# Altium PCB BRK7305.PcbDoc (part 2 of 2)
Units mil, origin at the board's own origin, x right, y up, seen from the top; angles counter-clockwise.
Board outline 4724.41 x 3149.61 mil, 4 copper layers (L1-TOP, L2-GND, L3-PWR, L4-BOT), stack 60.267 mil thick; 97 components, 177 nets, 610 pads, 294 vias.
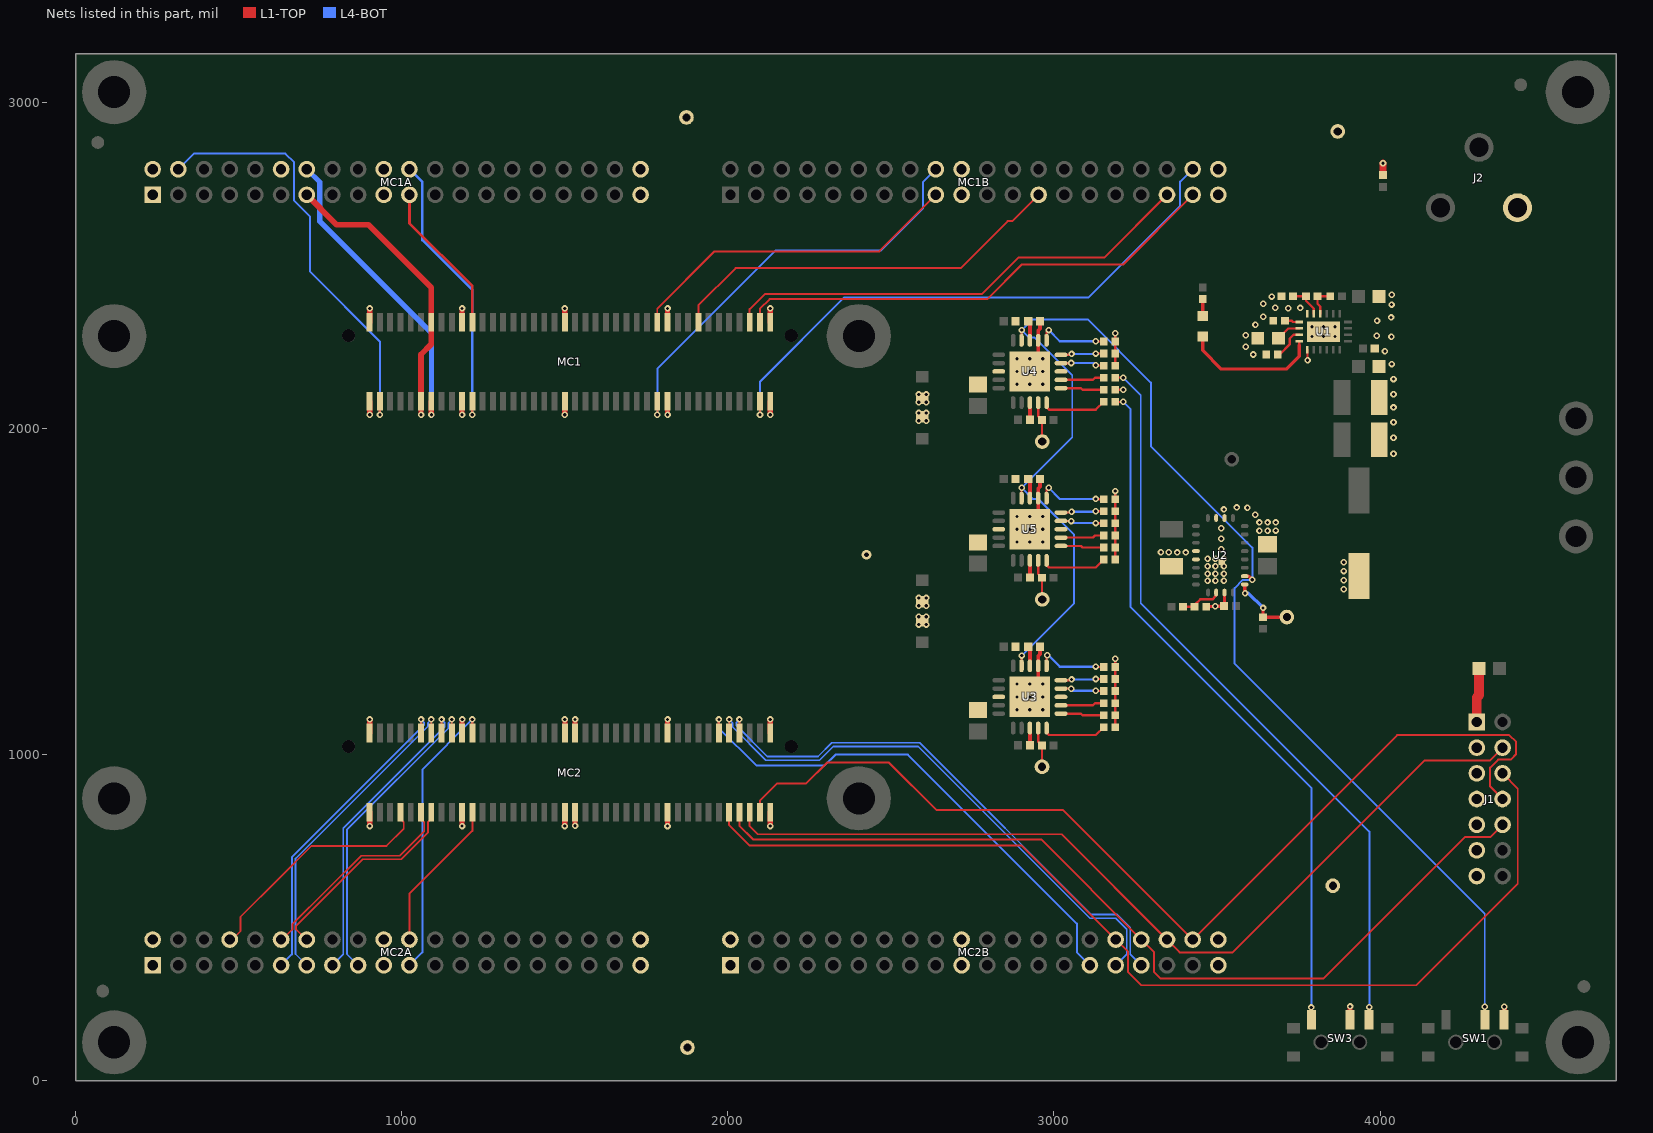
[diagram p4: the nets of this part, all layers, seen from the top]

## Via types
v1: diameter 20, hole 10, L1-TOP to L4-BOT, tented both sides, 293 vias
v2: diameter 30, hole 15, L1-TOP to L4-BOT, tented both sides, 1 vias

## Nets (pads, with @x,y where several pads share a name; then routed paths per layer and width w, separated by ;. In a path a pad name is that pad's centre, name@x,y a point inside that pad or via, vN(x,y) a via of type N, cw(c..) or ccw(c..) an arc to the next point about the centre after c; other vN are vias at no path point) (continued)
B34_L21P: MC2.8 MC2A.8 | length 754.5
  L1-TOP w5.25: MC2A.8@472.44,433.07 479.82,433.07 505.75,459 505.75,502.66 626.09,623 723.34,720.25 953.25,720.25 1006,773 1006,793 996.06,802.94 MC2.8@996.06,823.43
B34_L22N: MC2.14 MC2A.14 | length 646.3
  L1-TOP w5.25: MC2A.14@708.66,433.07 706.93,433.07 676,464 676,475 880,679 998.91,679 1080.25,760.34 1080.25,793 1090.55,803.3 MC2.14@1090.55,823.43
B34_L22P: MC2.12 MC2A.12 | length 648.3
  L1-TOP w5.25: MC2A.12@629.92,433.07 633.82,433.07 664.75,464 664.75,479.66 773.09,588 875.34,690.25 994.25,690.25 1069,765 1069,793 1059.06,802.94 MC2.12@1059.06,823.43
B34_L23N: MC2.17 MC2A.17 | length 942.8
  L1-TOP w5.25: MC2.17@1153.54,1066.34 v1(1153.54,1108)
  L4-BOT w5.25: MC2A.17@866.14,354.33 831.87,388.61 831.87,769.79 1143.42,1081.34 1143.42,1097.88 v1(1153.54,1108)
B34_L23P: MC2.15 MC2A.15 | length 942.3
  L1-TOP w5.25: MC2.15@1122.05,1066.34 v1(1122.05,1108)
  L4-BOT w5.25: MC2A.15@787.4,354.33 820.62,387.55 820.62,774.45 1132.17,1086 1132.17,1097.88 v1(1122.05,1108)
B34_L24N: MC2.13 MC2A.13 | length 981.9
  L1-TOP w5.25: MC2.13@1090.55,1066.34 v1(1090.55,1108)
  L4-BOT w5.25: MC2A.13@708.66,354.33 674.39,388.61 674.39,681.3 1080.43,1087.34 1080.43,1097.88 v1(1090.55,1108)
B34_L24P: MC2.11 MC2A.11 | length 981.5
  L1-TOP w5.25: MC2.11@1059.06,1066.34 v1(1059.06,1108)
  L4-BOT w5.25: MC2A.11@629.92,354.33 663.14,387.55 663.14,685.96 1069.18,1092 1069.18,1097.88 v1(1059.06,1108)
DGND: C1.1 C2.1 C3.2 C4.2 C5.2 C6.1 C7.1 C8.1 C9.1 C10.1 C11.1 C12.1 C14.1 C15.1 C16.1 C17.1 C18.1 C19.1 C20.1 C23.1 C24.1 J1.1 J1.3 J1.5 J1.7 J1.9 J1.11 J1.13 J2.2 MC1.1 MC1.2 MC1.19 MC1.20 MC1.39 MC1.40 MC1.59 MC1.60 MC1.79 MC1.80 MC1A.1 MC1A.2 MC1A.19 MC1A.20 MC1A.39 MC1A.40 MC1B.19 MC1B.20 MC1B.39 MC1B.40 MC2.1 MC2.2 MC2.19 MC2.20 MC2.39 MC2.40 MC2.59 MC2.60 MC2.79 MC2.80 MC2A.1 MC2A.2 MC2A.19 MC2A.20 MC2A.39 MC2A.40 MC2B.19 MC2B.20 MC2B.39 MC2B.40 R3.1 R4.1 R6.1 R7.1 R9.1 R11.1 R13.1 R14.1 R15.1 R16.1 R23.1 R25.1 R26.1 R28.1 R29.1 R30.1 R31.1 R32.1 R33.1 R34.1 SW1.3 SW3.2 TP6.1 TP7.1 TP8.1 TP9.1 U1.1 U1.16 U1.PAD U2.2 U2.3 U2.8 U2.9 U2.15 U2.PAD U3.0 U3.8 U3.12 U3.18 U4.0 U4.8 U4.12 U4.18 U5.0 U5.8 U5.12 U5.18 | length 2290
  L1-TOP w7: R4.1@3187.72,1084 R9.1@3187.72,1195 R11.1@3187.72,1232 R13.1@3187.72,1269 3187.72,1293.72 v1(3188,1294) ; R23.1@3187.72,1598.18 R26.1@3187.72,1635.18 R28.1@3187.72,1672.18 R30.1@3187.72,1709.18 R32.1@3187.72,1746.18 R34.1@3187.72,1783.18 3187.72,1807.9 v1(3188,1808.18) ; R25.1@3187.72,2119 v1(3212,2119) ; R29.1@3187.72,2193 R31.1@3187.72,2230 R33.1@3187.72,2267 3187.72,2291.72 v1(3188,2292) ; U1.1@3777.19,2242.02 3777.19,2209.35 v1(3777.41,2209.14)
  L1-TOP w10: R3.1@3466.43,1454 3493,1454 v1(3494.44,1455.44) C14.1@3521.62,1455.44 ; C14.1@3522.87,1456.44 U2.15@3522.87,1497.27 ; v1(4008.8,2813.45) v1@4009,2813.25
  L1-TOP w12: v1(2926,1177) 2951.59,1202.59 U3.12@2951.59,1272.47 2951.59,1302.59 2957.11,1308.11 C15.1@2957.11,1329 ; v1(2926,1691.18) 2951.59,1716.77 U5.12@2951.59,1786.65 2951.59,1816.77 2957.11,1822.29 C24.1@2957.11,1843.18 ; v1(2926,2175) 2951.59,2200.59 U4.12@2951.59,2270.47 2951.59,2300.59 2957.11,2306.11 C23.1@2957.11,2327
  L1-TOP w15: MC2.39@1500,1066.34 v1(1500,1108) ; SW3.2@3908,187.53 v1(3908,228) ; SW1.3@4379.92,187.01 4381,188.09 v1(4381,227)
  L1-TOP w16: v1(901.51,781.09) v1(901.51,781.09) MC2.2@901.58,823.43 ; MC2.1@901.58,1066.34 901.58,1108 v1(901.64,1108) ; v1(901.58,2042) MC1.2@901.58,2083.27 ; MC1.1@901.58,2326.18 v1(901.58,2368.46) ; v1(1184.98,781.09) 1185.04,781.09 MC2.20@1185.04,823.43 ; MC2.19@1185.04,1066.34 1185.04,1108 v1(1185.1,1108) ; v1(1185.04,2042) MC1.20@1185.04,2083.27 ; MC1.19@1185.04,2326.18 v1(1185.04,2368.46) ; v1(1499.94,781.09) 1500,781.09 MC2.40@1500,823.43 ; v1(1500,2042) MC1.40@1500,2083.27 ; MC1.39@1500,2326.18 v1(1500,2368.46) ; v1(1814.9,781.09) v1(1814.9,781.09) MC2.60@1814.96,823.43 ; MC2.59@1814.96,1066.34 1814.96,1108 v1(1815.02,1108) ; v1(1814.96,2042) MC1.60@1814.96,2083.27 ; MC1.59@1814.96,2326.18 v1(1814.96,2368.46) ; v1(2129.92,781.09) MC2.80@2129.92,823.43 ; MC2.79@2129.92,1066.34 v1(2129.92,1108) ; v1(2129.92,2042) MC1.80@2129.92,2083.27 ; MC1.79@2129.92,2326.18 v1(2129.92,2368.46)
  L1-TOP w22: C6.1@4009,2777.11 v1@4009,2813.25
  L1-TOP w30: J1.1@4296.63,1100.22 4296.63,1175.13 4303.5,1182 C1.1@4303.5,1264
  other v1: 2886.63,1137.63 2926,1137.63 2965.37,1137.63 2886.63,1177 2965.37,1177 2886.63,1216.37 2926,1216.37 2965.37,1216.37 3888.39,1507.4 3471,1533 3495,1533 3521,1533 3888.39,1534.86 3471,1555 3495,1555 3521,1555 3888.39,1562.86 3471,1578 3495,1578 3521,1578 3888.39,1589.86 3471,1601 3495,1601 3521,1601 3378,1620 3404,1620 3328,1621 3352,1621 3513,1630 2886.63,1651.81 2926,1651.81 2965.37,1651.81 3513,1662 3630,1687 3655,1687 3680,1687.26 2886.63,1691.18 2965.37,1691.18 3513,1694 3630,1712 3655,1712 3680,1712 2886.63,1730.55 2926,1730.55 2965.37,1730.55 3617,1736 3521,1752 3593,1757 3560,1758 4041,1923 4041,1971.64 4041,2019.64 4041,2064.64 4041,2105.14 2886.63,2135.63 2926,2135.63 2965.37,2135.63 4041,2151.64 2886.63,2175 2965.37,2175 4035.61,2197.64 2886.63,2214.37 2926,2214.37 2965.37,2214.37 3610.91,2227.04 4014.61,2236.64 3588.21,2250.64 3791.41,2282.14 3826.41,2282.14 3861.41,2282.14 4034.61,2281.64 3989.61,2284.64 3587.81,2286.44 3791.41,2312.14 3826.41,2312.14 3861.41,2312.14 3617.81,2318.34 3990.61,2330.64 4033.61,2340.64 3641.51,2343.04 3718.61,2368.64 3755.41,2369.84 3678.61,2370.64 4035,2380 3641.61,2382.64 3667.71,2404.74 4036,2410
  other v2: 2425,1613
FPGA_TCK: J1.6 MC2.72 MC2B.32 | length 3184.1
  L1-TOP w6: MC2.72@2003.94,823.43 2003.94,784.06 2067,721 2901.05,721 MC2B.32@3188.98,433.07 3227,395.05 3227,333 3267,293 4111,293 4422.06,604.06 4422.06,896.06 J1.6@4375.37,942.74
FPGA_TDI: J1.10 MC2.74 MC2B.34 | length 2807.1
  L1-TOP w6: MC2.74@2035.43,823.43 2035.43,781.57 2077,740 2960.79,740 MC2B.34@3267.72,433.07 3307,393.79 3307,333 3327,313 3826,313 4260,747 4337.11,747 J1.10@4375.37,785.26
FPGA_TDO: J1.8 MC2.78 MC2B.38 | length 3141.8
  L1-TOP w6: MC2.78@2098.43,823.43 2098.43,858.43 2152,912 2240,912 2304,976 2494,976 2639,831 3027.27,831 MC2B.38@3425.2,433.07 4052.13,1060 4396,1060 4417,1039 4417,1002 4400,985 4362,985 4337,960 4337,902.37 J1.8@4375.37,864
FPGA_TMS: J1.4 MC2.76 MC2B.36 | length 2771
  L1-TOP w6: MC2.76@2066.93,823.43 2066.93,781.07 2092,756 3023.53,756 MC2B.36@3346.46,433.07 3385.53,394 3548,394 4136,982 4335.89,982 J1.4@4375.37,1021.48
MC1_4: MC1.4 MC1A.4 | length 1311
  L1-TOP w8: v1@933.07,2041.61 MC1.4@933.07,2083.27
  L4-BOT w6: MC1A.4@314.96,2795.28 362.69,2843 643,2843 670,2816 670,2699 718,2651 718,2482 933.07,2266.93 v1@933.07,2041.61
  other v1: 933.07,2042
MC1_21: MC1.21 MC1A.21 | length 470.3
  L1-TOP w8: MC1A.21@1023.62,2716.54 1023.62,2629.38 1216.54,2436.46 MC1.21@1216.54,2326.18
MC1_22: MC1.22 MC1A.22 | length 875.2
  L1-TOP w8: v1@1216.54,2041.61 MC1.22@1216.54,2083.27
  L4-BOT w8: MC1A.22@1023.62,2795.28 1063,2755.9 1063,2578 1216.54,2424.46 v1@1216.54,2041.61
  other v1: 1216.54,2042
MC1_57: MC1.57 MC1B.17 | length 1040.2
  L1-TOP w6: MC1.57@1783.46,2326.18 1783.46,2367.47 1959,2543 2464.26,2543 MC1B.17@2637.8,2716.54
MC1_58: MC1.58 MC1B.18 | length 1337.6
  L1-TOP w6: MC1.58@1783.46,2083.27 1783.54,2083.2 v1(1783.54,2042)
  L4-BOT w6: v1(1783.54,2042) 1783.54,2183.54 2146.63,2546.63 2469.63,2546.63 2599,2676 2599,2756.48 MC1B.18@2637.8,2795.28
MC1_65: MC1.65 MC1B.25 | length 1235
  L1-TOP w6: MC1.65@1909.45,2326.18 1909.45,2377.45 2024,2492 2714,2492 2858,2636 2872.22,2636 MC1B.25@2952.76,2716.54
MC1_75: MC1.75 MC1B.35 | length 1464.5
  L1-TOP w6: MC1.75@2066.93,2326.18 2066.93,2365.93 2113,2412 2779,2412 2891,2524 3153.92,2524 MC1B.35@3346.46,2716.54
MC1_77: MC1.77 MC1B.37 | length 1512.6
  L1-TOP w6: MC1.77@2098.43,2326.18 2098.43,2367.43 2128,2397 2795,2397 2901,2503 3211.66,2503 MC1B.37@3425.2,2716.54
MC1_78: MC1.78 MC1B.38 | length 1782.9
  L1-TOP w6: MC1.78@2098.43,2083.27 2098.43,2042.07 v1(2098.5,2042)
  L4-BOT w6: v1(2098.5,2042) 2098.5,2143.5 2357,2402 3106,2402 3387,2683 3387,2757.08 MC1B.38@3425.2,2795.28
MC2_21: MC2.21 MC2A.21 | length 875.2
  L1-TOP w8: MC2.21@1216.54,1066.34 v1(1216.54,1108)
  L4-BOT w6: MC2A.21@1023.62,354.33 1063,393.71 1063,954.46 v1(1216.54,1108)
MC2_22: MC2.22 MC2A.22 | length 470.3
  L1-TOP w6: MC2A.22@1023.62,433.07 1023.62,573.62 1216.54,766.54 MC2.22@1216.54,823.43
MC2_69: MC2.69 MC2B.29 | length 1585.7
  L1-TOP w8: MC2.69@1972.44,1066.34 v1(1972.44,1108)
  L4-BOT w6: v1(1972.44,1108) 1972.44,1081.56 2087,967 2297,967 2330,1000 2552,1000 3070,482 3070,394.57 MC2B.29@3110.24,354.33
NetC13_1: C13.1 U3.3 | length 52.6
  L1-TOP w12: U3.3@2926,1081.53 2926.11,1081.42 C13.1@2926.11,1029
NetC15_2: C15.2 U3.13 | length 58.6
  L1-TOP w12: C15.2@2920.89,1329 2926,1323.89 U3.13@2926,1272.47
NetC16_2: C16.2 U1.18 | length 76.1
  L1-TOP w7: C16.2@3687.9,2276.94 3717.94,2306.98 U1.18@3751.6,2306.98
NetC21_1: C21.1 U4.3 | length 52.6
  L1-TOP w12: U4.3@2926,2079.53 2926.11,2079.42 C21.1@2926.11,2027
NetC22_1: C22.1 U5.3 | length 52.6
  L1-TOP w12: U5.3@2926,1595.71 2926.11,1595.6 C22.1@2926.11,1543.18
NetC23_2: C23.2 U4.13 | length 58.6
  L1-TOP w12: C23.2@2920.89,2327 2926,2321.89 U4.13@2926,2270.47
NetC24_2: C24.2 U5.13 | length 58.6
  L1-TOP w12: C24.2@2920.89,1843.18 2926,1838.07 U5.13@2926,1786.65
NetD1_1: D1.1 U1.20 | length 424.5
  L1-TOP w7: U1.20@3751.6,2267.61 3751.76,2267.46 3751.76,2255.49
  L1-TOP w10: D1.1@3455.76,2281.99 3455.76,2239.49 3512.76,2182.49 3712.76,2182.49 3751.76,2221.49 3751.76,2255.49
NetD1_2: D1.2 R8.1 | length 53.1
  L1-TOP w10: D1.2@3455.76,2344.98 3455.76,2397.41 R8.1@3456.21,2397.86
NetR1_1: R1.1 R3.2 U2.14 | length 128
  L1-TOP w8: R1.1@3395.43,1454 R3.2@3431,1454 3431,1459 3448.46,1476.46 3485.46,1476.46 3497.28,1488.28 U2.14@3497.28,1497.27
NetR2_1: R2.1 R10.2 U1.14 | length 96.7
  L1-TOP w7: U1.14@3816.56,2352.26 3816.56,2373.98 3807.92,2382.62 R10.2@3807.92,2405.84 R2.1@3847.49,2405.84
NetR4_2: R4.2 U3.5 | length 202
  L1-TOP w7: U3.5@2977.18,1081.53 2977.18,1067.82 2985,1060 3128.28,1060 R4.2@3152.28,1084
NetR5_1: R5.1 TP1.1 U3.4 | length 123.7
  L1-TOP w7: U3.4@2951.59,1081.53 2951.59,1039.69 R5.1@2963.28,1028 TP1.1@2963.28,962.72
NetR6_2: R6.2 U3.6 | length 132.8
  L1-TOP w7: U3.6@3021.47,1125.82 3082.82,1125.82 3087.64,1121 R6.2@3152.28,1121
NetR7_2: R7.2 U3.7 | length 133.5
  L1-TOP w7: U3.7@3021.47,1151.41 3119.41,1151.41 3126,1158 R7.2@3152.28,1158
NetR9_2: R9.2 U3.9 | length 134
  L1-TOP w7: U3.9@3021.47,1202.59 3052.41,1202.59 v1(3053,1202) ; v1(3128,1196) 3129,1195 R9.2@3152.28,1195
  L4-BOT w7: v1(3053,1202) 3059,1196 v1(3128,1196)
NetR10_1: R10.1 R15.2 U1.15 | length 103.3
  L1-TOP w7: R15.2@3732.92,2405.84 R10.1@3772.49,2405.84 3772.49,2392.05 3796.88,2367.67 U1.15@3796.88,2352.26
NetR11_2: R11.2 U3.10 | length 135.3
  L1-TOP w7: U3.10@3021.47,1228.18 3052.82,1228.18 3054,1229.36 v1(3054,1230.63) ; v1(3128,1232) R11.2@3152.28,1232
  L4-BOT w7: v1(3054,1230.63) 3121.37,1230.63 3124,1228 v1(3128,1232)
NetR12_1: R12.1 TP2.1 U2.17 | length 202.4
  L1-TOP w10: U2.17@3584.88,1521.87 3584.88,1496.12 v1(3586,1495) ; v1(3641,1450) R12.1@3641,1421.72 3713.72,1421.72 TP2.1@3714,1422
  L4-BOT w10: v1(3586,1495) 3596,1495 v1(3641,1450)
NetR13_2: R13.2 U3.11 | length 221.5
  L1-TOP w7: U3.11@2977.18,1272.47 2977.18,1303.18 v1(2979,1305) ; v1(3128,1270) 3129,1269 R13.2@3152.28,1269
  L4-BOT w7: v1(2979,1305) 2983,1305 3018,1270 v1(3128,1270)
NetR14_2: R14.2 U1.19 | length 95
  L1-TOP w7: R14.2@3692.03,2227.14 3722.51,2257.62 3722.51,2275.64 3734.16,2287.3 U1.19@3751.6,2287.3
NetR16_2: R16.2 U1.17 | length 44.9
  L1-TOP w7: R16.2@3708.12,2330.14 3729.41,2330.14 3732.88,2326.67 U1.17@3751.6,2326.67
NetR21_1: R21.1 SW3.1 | length 2157.9
  L1-TOP w6: R21.1@3187.72,2082 v1(3212,2082)
  L1-TOP w8: SW3.1@3789,187.38 v1(3789,225)
  L4-BOT w6: v1(3212,2082) 3235,2059 3235,1452 3789,898 v1(3789,225)
NetR21_2: R21.2 U4.5 | length 202
  L1-TOP w7: U4.5@2977.18,2079.53 2977.18,2065.82 2985,2058 3128.28,2058 R21.2@3152.28,2082
NetR22_1: R22.1 TP3.1 U4.4 | length 123.7
  L1-TOP w7: U4.4@2951.59,2079.53 2951.59,2037.69 R22.1@2963.28,2026 TP3.1@2963.28,1960.72
NetR23_2: R23.2 U5.5 | length 202
  L1-TOP w7: U5.5@2977.18,1595.71 2977.18,1582 2985,1574.18 3128.28,1574.18 R23.2@3152.28,1598.18
NetR24_1: R24.1 TP4.1 U5.4 | length 124.7
  L1-TOP w7: U5.4@2951.59,1595.71 2951.59,1553.87 R24.1@2963.28,1542.18 2963.28,1476.9 TP4.1@2964,1476.18
NetR25_2: R25.2 U4.6 | length 132.8
  L1-TOP w7: U4.6@3021.47,2123.82 3082.82,2123.82 3087.64,2119 R25.2@3152.28,2119
NetR26_2: R26.2 U5.6 | length 132.8
  L1-TOP w7: U5.6@3021.47,1640 3082.82,1640 3087.64,1635.18 R26.2@3152.28,1635.18
NetR27_1: R27.1 SW3.3 | length 2305.5
  L1-TOP w6: R27.1@3187.72,2156 v1(3212,2156)
  L1-TOP w8: SW3.3@3967,187.47 v1(3967,226)
  L4-BOT w6: v1(3212,2156) 3266,2102 3266,1465 3967,764 v1(3967,226)
NetR27_2: R27.2 U4.7 | length 133.5
  L1-TOP w7: U4.7@3021.47,2149.41 3119.41,2149.41 3126,2156 R27.2@3152.28,2156
NetR28_2: R28.2 U5.7 | length 133.5
  L1-TOP w7: U5.7@3021.47,1665.59 3119.41,1665.59 3126,1672.18 R28.2@3152.28,1672.18
NetR29_2: R29.2 U4.9 | length 134.3
  L1-TOP w7: U4.9@3021.47,2200.59 3052.59,2200.59 v1(3053,2201) ; v1(3128,2194) 3129,2193 R29.2@3152.28,2193
  L4-BOT w7: v1(3053,2201) 3121,2201 v1(3128,2194)
NetR30_2: R30.2 U5.9 | length 134
  L1-TOP w7: U5.9@3021.47,1716.77 3052.41,1716.77 v1(3053,1716.18) ; v1(3128,1710.18) 3129,1709.18 R30.2@3152.28,1709.18
  L4-BOT w7: v1(3053,1716.18) 3059,1710.18 v1(3128,1710.18)
NetR31_2: R31.2 U4.10 | length 136.9
  L1-TOP w7: U4.10@3021.47,2226.18 3052.82,2226.18 3054,2227.36 v1(3054,2228.63) ; v1(3128,2230) R31.2@3152.28,2230
  L4-BOT w7: v1(3054,2228.63) v1@3126.63,2228.63 ; v1@3124,2226 v1(3128,2230)
NetR32_2: R32.2 U5.10 | length 135.3
  L1-TOP w7: U5.10@3021.47,1742.36 3052.82,1742.36 3054,1743.54 v1(3054,1744.81) ; v1(3128,1746.18) R32.2@3152.28,1746.18
  L4-BOT w7: v1(3054,1744.81) 3121.37,1744.81 3124,1742.18 v1(3128,1746.18)
NetR33_2: R33.2 U4.11 | length 217.1
  L1-TOP w7: U4.11@2977.18,2270.47 2977.18,2295.18 v1(2984,2302) ; v1(3128,2268) 3129,2267 R33.2@3152.28,2267
  L4-BOT w7: v1(2984,2302) 3018,2268 v1(3128,2268)
NetR34_2: R34.2 U5.11 | length 217.1
  L1-TOP w7: U5.11@2977.18,1786.65 2977.18,1811.36 v1(2984,1818.18) ; v1(3128,1784.18) 3129,1783.18 R34.2@3152.28,1783.18
  L4-BOT w7: v1(2984,1818.18) 3018,1784.18 v1(3128,1784.18)
PWR_EN: SW1.2 U2.18 U3.14 U4.14 U5.14 | length 4332.6
  L1-TOP w6: SW1.2@4320.87,187.01 v1(4320.87,227)
  L1-TOP w7: U3.14@2900.41,1272.47 2900.41,1303.41 v1(2901,1304) ; U5.14@2900.41,1786.65 2900.41,1817.59 v1(2901,1818.18) ; U4.14@2900.41,2270.47 2900.41,2301.41 v1(2901,2302)
  L1-TOP w10: U2.18@3584.88,1547.46 3596.54,1547.46 v1(3608,1536)
  L4-BOT w6: v1(2901,1304) 3062,1465 3062,1674 2952,1784 2935.18,1784 v1(2901,1818.18) 3056,1973.18 3056,2164 2941,2279 2924,2279 v1(2901,2302) 2934,2335 3103,2335 3297,2141 3297,1946 3608,1635 v1(3608,1536) 3579,1536 3554,1511 3554,1279 4320.87,512.13 v1(4320.87,227)
VCCBATT: MC1.14 MC1A.14 | length 953.1
  L1-TOP w16: MC1.14@1090.55,2083.27 1090.55,2042.45 v1(1091,2042)
  L4-BOT w16: MC1A.14@708.66,2795.28 748.81,2755.13 748.81,2635.19 1091,2293 v1(1091,2042)
VCCO_MC1: MC1.12 MC1.13 MC1A.12 MC1A.13 R17.2 R18.1 | length 904.1
  L1-TOP w8: v1@1059.06,2040.99 v1(1059.06,2042) v1@1059.06,2045
  L1-TOP w16: v1@1059.06,2045 MC1.12@1059.06,2083.27
  L1-TOP w18: MC1A.13@708.66,2716.54 800.2,2625 898,2625 1090.55,2432.45 MC1.13@1090.55,2326.18 1090.55,2258.55 1059.06,2227.06 MC1.12@1059.06,2083.27
  other v1: 2585,2023.93 2608,2023.93 2585,2047.93 2608,2047.93 2585,2080.46 2608,2080.46 2585,2104.46 2608,2104.46
VCCO_MC2: MC2.41 MC2.42 MC2B.1 MC2B.2 R19.2 R20.1 | length 83.1
  L1-TOP w16: v1(1531.5,782) MC2.42@1531.5,823.43 ; MC2.41@1531.5,1066.34 v1(1531.5,1108)
  other v1: 2585,1398.93 2608,1398.93 2585,1422.93 2608,1422.93 2585,1456.46 2608,1456.46 2585,1480.46 2608,1480.46
XADC_VN: MC2.73 MC2B.33 | length 1693.7
  L1-TOP w5.25: MC2.73@2035.43,1066.34 v1(2035.43,1108)
  L4-BOT w5.25: v1(2035.43,1108) 2025.31,1097.88 2025.31,1090 2121.06,994.25 2276.25,994.25 2318.25,1036.25 2588.66,1036.25 3114.91,510 3193.91,510 3234.25,469.66 3234.25,387.8 MC2B.33@3267.72,354.33
XADC_VP: MC2.71 MC2B.31 | length 1694
  L1-TOP w5.25: MC2.71@2003.94,1066.34 v1(2003.94,1108)
  L4-BOT w5.25: v1(2003.94,1108) 2014.06,1097.88 2014.06,1085.34 2116.4,983 2280.91,983 2322.91,1025 2584,1025 3110.25,498.75 3189.25,498.75 3223,465 3223,388.35 MC2B.31@3188.98,354.33
pads on no net: FID1.FID? FID2.FID? FID3.FID? FID4.FID? J1.12 J1.14 J2.3 MC1.81 MC1.82 MC2.81 MC2.82 MH1.1 MH2.1 MH3.1 MH4.1 MH5.1 MH6.1 MH7.1 MH8.1 SW1.0 SW3.0 U1.2 U1.3 U2.1 U2.21 U2.22 U2.23 U2.24

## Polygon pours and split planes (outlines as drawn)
+VDC on L3-PWR "L3_+VDC" (solid, pour order 52): 4685,2363 4685,456 4389,160 3946,160 3158,948 2993,948 2665,1276 2665,2363
+1.0VDD on L3-PWR "L3_+1.0VDD" (solid, pour order 48): 355,2839 355,2198 1009,1544 3425.19,1544 3425.19,1811 2826,1811 2665,1972 2665,2008 1038,2008 1038,2839
VCCO_MC1 on L3-PWR "L3_VCCO_MC1" (solid, pour order 46): 591,2839 3557,2839 3557,2678 3557,2373 2801,2373 2665,2237 2665,2019 1048,2019 1048,2256 673,2631 673,2677 591,2759
VCCO_MC2 on L3-PWR "L3_VCCO_MC2" (solid, pour order 50): 289,304 289,591 1192,1494 2627,1494 2627,1231 2982,876 3162,876 3554,484 3554,304
+5VDC on L4-BOT "L4_+5VDC" (solid, pour order 54): 4661,2284 3905,2284 3802,2181 3802,1916 3970,1748 4382,1748 4565,1931 4661,1931
DGND on L2-GND (split plane): 4704.31,20.1 20.1,20.1 20.1,3129.51 4704.31,3129.51

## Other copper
L1-TOP:
  rectangle net DGND: 3878,1478 3967,1618
  rectangle net VCCO_MC1: 2572,2070.46 2620,2114.46
  rectangle net VCCO_MC1: 2572,2013.93 2620,2057.93
  rectangle net +1.8VDD: 2572,1513.39 2620,1557.39
  rectangle net VCCO_MC2: 2572,1446.46 2620,1490.46
  rectangle net VCCO_MC2: 2572,1388.93 2620,1432.93
  rectangle net +3.3VDD: 2572,1322 2620,1366
  region net +VDCIN: 4236,2742 3871.25,2742 3871.25,2392.75 3856,2377.5 3846.5,2377.5 3833,2364 3833,2341 3879,2341 3890,2330 3890,2304 3953,2304 3953,2434 3972,2453 4236,2453
  region net DGND: 3970.41,2424 4054,2424 4054,1911.14 3970.41,1911.14 3970.41,2232.14 3970.41,2378.14
  region net +5VDC: 3888.41,2291 3888.41,2262.14 3880.41,2254.14 3831.41,2254.14 3831.41,2225.14 3857.41,2199.14 3857.41,2152 3769,2152 3769,1741 3967,1741 3967,1880 3929,1880 3929,2141.73 3958,2170.73 3958,2291
  region net DGND: 3575.71,2209 3575.71,2294.94 3628.21,2347.44 3628.21,2389.74 3655.47,2417 3709,2417 3709,2397 3723.06,2382.94 3762.34,2382.94 3781,2364.28 3781,2341 3759.64,2341 3746.21,2354.44 3694.44,2354.44 3684,2344 3684,2309 3652,2309 3652,2249 3662,2239 3662,2209
  region net DGND: 3442,1593 3428,1593 3396,1561 3396,1552 3318,1552 3318,1632 3424,1632 3426,1630 3442,1630
  region net +VDC: 3577,1604 3577,1568 3602,1568 3624.89,1545.11 3624.89,1496.44 3696,1496.44 3696,1604
  region net DGND: 3531,1716 3531,1747 3585,1747 3612,1720 3612,1621 3696,1621 3696,1778 3497,1778 3497,1716
  region net +1.0VDD: 3476,1741 3326,1741 3326,1656 3409,1656 3421,1644 3453,1644 3453,1710 3476,1710
  region net DGND: 2870,2317 2894,2317 2894,2347.63 2978.37,2347.63 3002,2324 3002,2243.63 3069,2243.63 3069,2185 2953,2185 2953,2163.63 3112,2163.63 3112,2399 2870,2399
  region net DGND: 2740,2118.63 2794,2118.63 2794,2168 2894,2168 2894,2181 2740,2181
  region net +VDD_DDR3: 2740,2093.63 2806,2093.63 2806,2155.63 2855,2155.63 2855,2103.63 2912,2103.63 2912,2056.63 2902,2046.63 2902,2014.63 2740,2014.63
  region net +VDC: 2858,2359.63 2858,2303 2886,2303 2886,2246.63 2854,2246.63 2854,2194.63 2807,2194.63 2807,2359.63
  region net +VDC: 2858,1875.81 2858,1819 2886,1819 2886,1762.81 2854,1762.81 2854,1710.81 2807,1710.81 2807,1875.81
  region net +1.8VDD: 2740,1609.81 2806,1609.81 2806,1671.81 2855,1671.81 2855,1619.81 2912,1619.81 2912,1572.81 2902,1562.81 2902,1530.81 2740,1530.81
  region net DGND: 2740,1634.81 2794,1634.81 2794,1685 2894,1685 2894,1698 2740,1698
  region net DGND: 2870,1833.18 2894,1833.18 2894,1863.81 2978.37,1863.81 3001,1841.18 3001,1759.81 3069,1759.81 3069,1701 2953,1701 2953,1679.81 3112,1679.81 3112,1915.18 2870,1915.18
  region net +VDC: 2858,1361.63 2858,1305 2886,1305 2886,1248.63 2854,1248.63 2854,1196.63 2807,1196.63 2807,1361.63
  region net +3.3VDD: 2740,1095.63 2806,1095.63 2806,1157.63 2855,1157.63 2855,1105.63 2912,1105.63 2912,1058.63 2902,1048.63 2902,1016.63 2740,1016.63
  region net DGND: 2740,1120.63 2794,1120.63 2794,1171 2894,1171 2894,1183 2740,1183
  region net DGND: 2870,1319 2894,1319 2894,1349.63 2978.37,1349.63 2996,1332 2996,1245.63 3069,1245.63 3069,1187 2953,1187 2953,1165.63 3112,1165.63 3112,1401 2870,1401

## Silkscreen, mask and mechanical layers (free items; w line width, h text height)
Top Overlay:
  lines w7.99: 25,748.03 2519.69,748.03 2519.69,2401.58 25,2401.58
  lines w10: 3873,253 3857,269 ; 3873,285 3857,269 ; 3922,253 3938,269 ; 3922,285 3938,269 ; 4149,1834 4165,1818 ; 4149,1883 4165,1899 ; 4181,1834 4165,1818 ; 4181,1883 4165,1899 ; 4248,254 4232,270 ; 4248,286 4232,270 ; 4297,254 4313,270 ; 4297,286 4313,270 ; 3857,269 3938,269 ; 4165,1818 4165,1899 ; 4232,270 4313,270
  text "+5VDC" at 4382,2879 h40
  text "B15_L19P" at 807.09,2855 h30 r90
  text "DGND" at 255.91,2854.33 h30 r90
  text "MC1_4" at 334.65,2854.33 h30 r90
  text "+1.0VDD" at 413.39,2854.33 h30 r90
  text "+1.0VDD" at 492.13,2854.33 h30 r90
  text "+1.0VDD" at 570.87,2854.33 h30 r90
  text "VCCO_MC1" at 649.61,2854.33 h30 r90
  text "VCCBATT" at 728.35,2854.33 h30 r90
  text "B15_L19N" at 885.83,2854.33 h30 r90
  text "DGND" at 964.57,2854.33 h30 r90
  text "MC1_22" at 1043.31,2854.33 h30 r90
  text "B15_L23P" at 1122.05,2854.33 h30 r90
  text "B15_L23N" at 1200.79,2854.33 h30 r90
  text "B15_L24P" at 1279.53,2854.33 h30 r90
  text "B15_L24N" at 1358.27,2854.33 h30 r90
  text "B15_L20P" at 1437.01,2854.33 h30 r90
  text "B15_L20N" at 1515.75,2854.33 h30 r90
  text "B15_L16P" at 1594.49,2854.33 h30 r90
  text "B15_L16N" at 1673.23,2854.33 h30 r90
  text "DGND" at 1751.97,2854.33 h30 r90
  text "B15_L22P" at 2027.56,2854.33 h30 r90
  text "B15_L22N" at 2106.3,2854.33 h30 r90
  text "B15_L10P" at 2185.04,2854.33 h30 r90
  text "B15_L10N" at 2263.78,2854.33 h30 r90
  text "B15_L15P" at 2342.52,2854.33 h30 r90
  text "B15_L15N" at 2421.26,2854.33 h30 r90
  text "B15_L8P" at 2500,2854.33 h30 r90
  text "B15_L8N" at 2578.74,2854.33 h30 r90
  text "MC1_58" at 2657.48,2854.33 h30 r90
  text "DGND" at 2736.22,2854.33 h30 r90
  text "B15_L2P" at 2814.96,2854.33 h30 r90
  text "B15_L2N" at 2893.7,2854.33 h30 r90
  text "B15_L4P" at 2972.44,2854.33 h30 r90
  text "B15_L4N" at 3051.18,2854.33 h30 r90
  text "B15_L3P" at 3129.92,2854.33 h30 r90
  text "B15_L3N" at 3208.66,2854.33 h30 r90
  text "B15_L1P" at 3287.4,2854.33 h30 r90
  text "B15_L1N" at 3366.14,2854.33 h30 r90
  text "MC1_78" at 3444.88,2854.33 h30 r90
  text "DGND" at 3523.62,2854.33 h30 r90
  text "DGND" at 255.91,2547.25 h30 r90
  text "DGND" at 964.57,2547.25 h30 r90
  text "DGND" at 1751.97,2547.25 h30 r90
  text "DGND" at 2736.22,2547.25 h30 r90
  text "DGND" at 3523.62,2547.25 h30 r90
  text "MC1_21" at 1043.31,2502.27 h30 r90
  text "MC1_57" at 2657.48,2492.27 h30 r90
  text "MC1_65" at 2972.44,2492.27 h30 r90
  text "MC1_75" at 3366.14,2492.27 h30 r90
  text "MC1_77" at 3444.88,2492.27 h30 r90
  text "+5VUSB" at 334.65,2487.27 h30 r90
  text "+1.8VDD" at 492.13,2467.28 h30 r90
  text "+1.8VDD" at 570.87,2467.28 h30 r90
  text "+3.3VDD" at 413.39,2462.28 h30 r90
  text "B15_L9P" at 2027.56,2462.28 h30 r90
  text "B15_L9N" at 2106.3,2462.28 h30 r90
  text "B15_L6P" at 2185.04,2462.28 h30 r90
  text "B15_L7P" at 2500,2462.28 h30 r90
  text "B15_L5P" at 2814.96,2462.28 h30 r90
  text "B15_L5N" at 2893.7,2462.28 h30 r90
  text "B15_L6N" at 2263.78,2457.28 h30 r90
  text "B15_L7N" at 2578.74,2457.28 h30 r90
  text "B15_L11P" at 1594.49,2442.29 h30 r90
  text "B15_L11N" at 1673.23,2442.29 h30 r90
  text "VCCO_MC1" at 728.35,2437.29 h30 r90
  text "B15_L21P" at 807.09,2437.29 h30 r90
  text "B15_L21N" at 885.83,2437.29 h30 r90
  text "B15_L18P" at 1122.05,2437.29 h30 r90
  text "B15_L18N" at 1200.79,2437.29 h30 r90
  text "B15_L14P" at 1279.53,2437.29 h30 r90
  text "B15_L14N" at 1358.27,2437.29 h30 r90
  text "B15_L17P" at 1437.01,2437.29 h30 r90
  text "B15_L17N" at 1515.75,2437.29 h30 r90
  text "B15_L12P" at 2342.52,2437.29 h30 r90
  text "B15_L12N" at 2421.26,2437.29 h30 r90
  text "B15_L13P" at 3051.18,2437.29 h30 r90
  text "B15_L13N" at 3129.92,2437.29 h30 r90
  text "B15_IO_0" at 3208.66,2437.29 h30 r90
  text "+VDD_DDR3" at 649.61,2414.63 h28 r90
  text "B15_IO_25" at 3287.4,2407.3 h30 r90
  text "+5VDC" at 4145,2108 h40 r270
  text "POWER SELECT" at 4215,2070 h40 r270
  text "+5VUSB" at 4145,1794 h40 r270
  text "2:Vref" at 4476,1082 h40
  text "4:TMS" at 4476,1003 h40
  text "JTAG" at 4158,937 h40 r270
  text "6:TCK" at 4476,924 h40
  text "8:TDO" at 4476,843 h40
  text "10:TDI" at 4476,765 h40
  text "'.Assembly_Part_Num' / '.PCB_Revision'" at 3575,745 h30
  text "DGND" at 255.91,492.13 h30 r90
  text "B34_L16P" at 334.65,492.13 h30 r90
  text "B34_L16N" at 413.39,492.13 h30 r90
  text "B34_L21P" at 492.13,492.13 h30 r90
  text "B34_L21N" at 570.87,492.13 h30 r90
  text "B34_L22P" at 649.61,492.13 h30 r90
  text "B34_L22N" at 728.35,492.13 h30 r90
  text "B34_L19P" at 807.09,492.13 h30 r90
  text "B34_L19N" at 885.83,492.13 h30 r90
  text "DGND" at 964.57,492.13 h30 r90
  text "MC2_22" at 1043.31,492.13 h30 r90
  text "B34_L11P" at 1122.05,492.13 h30 r90
  text "B34_L11N" at 1200.79,492.13 h30 r90
  text "B34_L18P" at 1279.53,492.13 h30 r90
  text "B34_L18N" at 1358.27,492.13 h30 r90
  text "B34_L4P" at 1437.01,492.13 h30 r90
  text "B34_L4N" at 1515.75,492.13 h30 r90
  text "B34_L8P" at 1594.49,492.13 h30 r90
  text "B34_L8N" at 1673.23,492.13 h30 r90
  text "DGND" at 1751.97,492.13 h30 r90
  text "VCCO_MC2" at 2027.56,492.13 h30 r90
  text "B34_L10P" at 2106.3,492.13 h30 r90
  text "B34_L10N" at 2185.04,492.13 h30 r90
  text "B34_L1P" at 2263.78,492.13 h30 r90
  text "B34_L1N" at 2342.52,492.13 h30 r90
  text "B34_L3P" at 2421.26,492.13 h30 r90
  text "B34_L3N" at 2500,492.13 h30 r90
  text "B34_L5P" at 2578.74,492.13 h30 r90
  text "B34_L5N" at 2657.48,492.13 h30 r90
  text "DGND" at 2736.22,492.13 h30 r90
  text "B34_L2P" at 2814.96,492.13 h30 r90
  text "B34_L2N" at 2893.7,492.13 h30 r90
  text "B34_IO_25" at 2972.44,492.13 h30 r90
  text "B34_IO_0" at 3051.18,492.13 h30 r90
  text "+1.8VDD" at 3129.92,492.13 h30 r90
  text "FPGA_TCK" at 3208.66,492.13 h30 r90
  text "FPGA_TDI" at 3287.4,492.13 h30 r90
  text "FPGA_TMS" at 3366.14,492.13 h30 r90
  text "FPGA_TDO" at 3444.88,492.13 h30 r90
  text "DGND" at 3523.62,492.13 h30 r90
  text "SDRAM IO" at 3725,378 h40
  text "BRK Power" at 4120,378 h40
  text "Voltage" at 3747,320 h40
  text "Enable" at 4180,320 h40
  text "1.35" at 3704,250 h40
  text "1.5" at 3953,250 h40
  text "ON" at 4144,250 h40
  text "OFF" at 4334,250 h40
  text "DGND" at 255.91,182.05 h30 r90
  text "DGND" at 964.57,182.05 h30 r90
  text "DGND" at 1751.97,182.05 h30 r90
  text "DGND" at 2736.22,182.05 h30 r90
  text "DGND" at 3523.62,182.05 h30 r90
  text "MC2_69" at 3129.92,122.07 h30 r90
  text "MC2_21" at 1043.31,107.07 h30 r90
  text "B16_L6N" at 3051.18,97.08 h30 r90
  text "B34_L6P" at 1437.01,92.08 h30 r90
  text "B34_L6N" at 1515.75,92.08 h30 r90
  text "B34_L9P" at 1594.49,92.08 h30 r90
  text "B34_L9N" at 1673.23,92.08 h30 r90
  text "B34_L7P" at 2106.3,92.08 h30 r90
  text "B34_L7N" at 2185.04,92.08 h30 r90
  text "XADC_VP" at 3208.66,92.08 h30 r90
  text "XADC_VN" at 3287.4,92.08 h30 r90
  text "B16_L11P" at 2814.96,77.08 h30 r90
  text "B16_L11N" at 2893.7,77.08 h30 r90
  text "B34_L13P" at 3366.31,74.58 h29 r90
  text "B34_L13N" at 3445.05,74.58 h29 r90
  text "B16_L13P" at 2263.78,72.08 h30 r90
  text "B16_L13N" at 2342.52,72.08 h30 r90
  text "B16_L12P" at 2421.26,72.08 h30 r90
  text "B16_L12N" at 2500,72.08 h30 r90
  text "B16_L14P" at 2578.74,72.08 h30 r90
  text "B16_L14N" at 2657.48,72.08 h30 r90
  text "B16_L19N" at 2972.44,72.08 h30 r90
  text "B34_L17P" at 334.65,67.09 h30 r90
  text "B34_L17N" at 413.39,67.09 h30 r90
  text "B34_L14P" at 1122.05,67.09 h30 r90
  text "B34_L14N" at 1200.79,67.09 h30 r90
  text "B34_L15P" at 1279.53,67.09 h30 r90
  text "B34_L15N" at 1358.27,67.09 h30 r90
  text "B34_L20P" at 492.13,62.09 h30 r90
  text "B34_L20N" at 570.87,62.09 h30 r90
  text "B34_L24P" at 649.61,62.09 h30 r90
  text "B34_L24N" at 728.35,62.09 h30 r90
  text "B34_L23P" at 807.09,62.09 h30 r90
  text "B34_L23N" at 885.83,62.09 h30 r90
  text "VCCO_MC2" at 2027.56,62.09 h30 r90
Outline:
  the board outline again, w8
Fab Notes:
  drawing of 302 lines, arcs and shapes, not listed
  text "LAYER STACKUP TABLE" at 5281,3740 h50
  text "Layer" at 5307.15,3621 h50
  text "Name" at 5648.07,3621 h50
  text "Material" at 6422.19,3621 h50
  text "Thickness" at 7138,3621 h50
  text "Constant" at 7678.86,3621 h50
  text "Board Layer Stack" at 8153.08,3621 h50
  text "1" at 5307.15,3521 h50
  text "Top Overlay" at 5648.07,3521 h50
  text "1. MATERIAL SELECTION: /      4-LAYER, IT-180A OR EQUIVALENT, 62 MILS +/-10% THICK /      SURFACE FINISH: ENIG (ELECTROLESS NICKEL, IMMERSION GOLD) /  / 2. SOLDER RESIST: GREEN LPI /  / 3. SILKSCREEN: WHITE / DO NOT REMOVE OVER TENTED VIAS /  / 4. LOT CODE IDENTIFICATION: ADD TO SILKSCREEN /      FORMAT: YYWW (YY = 2-DIGIT YEAR, WW = 2-DIGIT WEEK) /       / 5. DRILL SIZES ARE FINISHED SIZE AFTER PLATING /  / 6. ELECTRICAL BARE BOARD TEST REQUIRED /  / 7. BOARD TO BE IMPEDANCE CONTROLLED. /      SEE CONTROLLED IMPEDANCE TABLE /      REFER TO '.Assembly_Part_Num'-PCBStackup.pdf /      SHORT TRACE IMPEDANCE MEASUREMENTS CAN DEFAULT TO TDR COUPONS /   / 8. PANELIZATION: /      2 PIECES PER ARRAY /      0.25-IN SOLID TAB ON ALL SIDES PLUS 2.0-MM ROUTING PATH /      MOUSE-BITES FOR BOARD SEPARATION INDICATED BY ::: /       / 9. ALL 10.00-MIL VIAS MUST BE PLATED OVER FILLED VIA (POFV) /  / 10. FABRICATE TO MEET EU ROHS DIRECTIVE. /      SUPPLIER TO ADD LEAD-FREE MARKING IN SILKSCREEN. /       / 11. UL CERTIFICATION MARK REQUIRED" at -419,3461 h50
  text "2" at 5307.15,3421 h50
  text "Top Solder" at 5648.07,3421 h50
  text "Solder Resist" at 6422.19,3421 h50
  text "0.40mil" at 7138,3421 h50
  text "3.5" at 7678.86,3421 h50
  text "3" at 5307.15,3321 h50
  text "L1-TOP" at 5648.07,3321 h50
  text "Copper" at 6422.19,3321 h50
  text "1.40mil" at 7138,3321 h50
  text "4" at 5307.15,3221 h50
  text "Dielectric1" at 5648.07,3221 h50
  text "IT180A" at 6422.19,3221 h50
  text "5.08mil" at 7138,3221 h50
  text "4.2" at 7678.86,3221 h50
  text ":::" at 3386,3212 h50 r180
  text ":::" at 1218,3206 h50 r180
  text "5" at 5307.15,3121 h50
  text "L2-GND" at 5648.07,3121 h50
  text "Copper" at 6422.19,3121 h50
  text "1.40mil" at 7138,3121 h50
  text "6" at 5307.15,3021 h50
  text "Dielectric 2" at 5648.07,3021 h50
  text "IT180A" at 6422.19,3021 h50
  text "44.49mil" at 7138,3021 h50
  text "4.2" at 7678.86,3021 h50
  text "7" at 5307.15,2921 h50
  text "L3-PWR" at 5648.07,2921 h50
  text "Copper" at 6422.19,2921 h50
  text "1.42mil" at 7138,2921 h50
  text "8" at 5307.15,2821 h50
  text "Dielectric 3" at 5648.07,2821 h50
  text "IT180A" at 6422.19,2821 h50
  text "5.08mil" at 7138,2821 h50
  text "4.2" at 7678.86,2821 h50
  text "9" at 5307.15,2721 h50
  text "L4-BOT" at 5648.07,2721 h50
  text "Copper" at 6422.19,2721 h50
  text "1.40mil" at 7138,2721 h50
  text "10" at 5307.15,2621 h50
  text "Bottom Solder" at 5648.07,2621 h50
  text "Solder Resist" at 6422.19,2621 h50
  text "0.40mil" at 7138,2621 h50
  text "3.5" at 7678.86,2621 h50
  text "11" at 5307.15,2521 h50
  text "Bottom Overlay" at 5648.07,2521 h50
  text ":::" at 4746,2398 h50 r270
  text ":::" at -19.69,2306.36 h50 r90
  text "CONTROLLED IMPEDANCE TABLE" at 6045,1856 h60
  text "Layer" at 6072,1681.26 h50
  text "Width / (mils)" at 7122,1641.26 h50
  text "Impedance / (ohms)" at 6472,1631.26 h50
  text "Spacing / (mils)" at 7492,1631.26 h50
  text "L1" at 6132,1521.26 h50
  text "100 Diff" at 6492,1521.26 h50
  text "5.25" at 7172,1521.26 h50
  text "6.00" at 7542,1521.26 h50
  text "L4" at 6132,1401.26 h50
  text "100 Diff" at 6492,1401.26 h50
  text "5.25" at 7172,1401.26 h50
  text "6.00" at 7542,1401.26 h50
  text ":::" at 4752,1012 h50 r270
  text ":::" at -21,921 h50 r90
  text ":::" at 1126.36,-59.06 h50
  text ":::" at 3294.36,-63 h50
Drill Drawing:
  drawing of 385 lines, arcs and shapes, not listed
  text "DRILL TABLE" at 3409,5688 h50
  text "Symbol" at 3424.97,5562 h60
  text "Count" at 3845.47,5562 h60
  text "Hole Size" at 4344.67,5562 h60
  text "Plated" at 5260.4,5562 h60
  text "Hole Type" at 5680.9,5562 h60
  text "Drill Layer Pair" at 6291.33,5562 h60
  text "Via/Pad" at 7281.64,5562 h60
  text "Pad Shape" at 7772.12,5562 h60
  text "Technology" at 8392.55,5562 h60
  text "1" at 3845.47,5437 h50
  text "15.00mil (0.381mm)" at 4344.67,5437 h50
  text "PTH" at 5260.4,5437 h50
  text "Round" at 5680.9,5437 h50
  text "L1-TOP - L4-BOT" at 6291.33,5437 h50
  text "Via" at 7281.64,5437 h50
  text "Rounded" at 7772.12,5437 h50
  text "v76h38m0mx0" at 8392.55,5437 h50
  text "H" at 3400.96,5429.01 h55.56
  text "3" at 3845.47,5312 h50
  text "59.06mil (1.500mm)" at 4344.67,5312 h50
  text "PTH" at 5260.4,5312 h50
  text "Round" at 5680.9,5312 h50
  text "L1-TOP - L4-BOT" at 6291.33,5312 h50
  text "Pad" at 7281.64,5312 h50
  text "Rounded" at 7772.12,5312 h50
  text "c225h150" at 8392.55,5312 h50
  text "A" at 3400.96,5304.01 h55.56
  text "3" at 3845.47,5187 h50
  text "65.00mil (1.651mm)" at 4344.67,5187 h50
  text "PTH" at 5260.4,5187 h50
  text "Round" at 5680.9,5187 h50
  text "L1-TOP - L4-BOT" at 6291.33,5187 h50
  text "Pad" at 7281.64,5187 h50
  text "Rounded" at 7772.12,5187 h50
  text "c267h165" at 8392.55,5187 h50
  text "4" at 3845.47,5062 h50
  text "35.43mil (0.900mm)" at 4344.67,5062 h50
  text "PTH" at 5260.4,5062 h50
  text "Round" at 5680.9,5062 h50
  text "L1-TOP - L4-BOT" at 6291.33,5062 h50
  text "Pad" at 7281.64,5062 h50
  text "Rounded" at 7772.12,5062 h50
  text "c120h90" at 8392.55,5062 h50
  text "F" at 3400.96,5054.01 h55.56
  text "4" at 3845.47,4937 h50
  text "40.16mil (1.020mm)" at 4344.67,4937 h50
  text "PTH" at 5260.4,4937 h50
  text "Round" at 5680.9,4937 h50
  text "L1-TOP - L4-BOT" at 6291.33,4937 h50
  text "Pad" at 7281.64,4937 h50
  text "Rounded" at 7772.12,4937 h50
  text "c102h102" at 8392.55,4937 h50
  text "C" at 3400.96,4929.01 h55.56
  text "8" at 3845.47,4812 h50
  text "98.43mil (2.500mm)" at 4344.67,4812 h50
  text "PTH" at 5260.4,4812 h50
  text "Round" at 5680.9,4812 h50
  text "L1-TOP - L4-BOT" at 6291.33,4812 h50
  text "Pad" at 7281.64,4812 h50
  text "Rounded" at 7772.12,4812 h50
  text "c500h250z318" at 8392.55,4812 h50
  text "B" at 3400.96,4804.01 h55.56
  text "9" at 3845.47,4687 h50
  text "25.00mil (0.635mm)" at 4344.67,4687 h50
  text "PTH" at 5260.4,4687 h50
  text "Round" at 5680.9,4687 h50
  text "L1-TOP - L4-BOT" at 6291.33,4687 h50
  text "Pad" at 7281.64,4687 h50
  text "Rounded" at 7772.12,4687 h50
  text "c114h64" at 8392.55,4687 h50
  text "174" at 3845.47,4562 h50
  text "31.50mil (0.800mm)" at 4344.67,4562 h50
  text "PTH" at 5260.4,4562 h50
  text "Round" at 5680.9,4562 h50
  text "L1-TOP - L4-BOT" at 6291.33,4562 h50
  text "Pad" at 7281.64,4562 h50
  text "(Mixed)" at 7772.12,4562 h50
  text "(Mixed)" at 8392.55,4562 h50
  text "293" at 3845.47,4437 h50
  text "10.00mil (0.254mm)" at 4344.67,4437 h50
  text "PTH" at 5260.4,4437 h50
  text "Round" at 5680.9,4437 h50
  text "L1-TOP - L4-BOT" at 6291.33,4437 h50
  text "Via" at 7281.64,4437 h50
  text "Rounded" at 7772.12,4437 h50
  text "v51h25m0mx0" at 8392.55,4437 h50
  text "499 Total" at 3845.47,4312 h50
  text "Layer" at 3609.59,-3700.37 h60
  text "Name" at 4019.5,-3700.37 h60
  text "Material" at 4949.24,-3700.37 h60
  text "Thickness" at 5809.01,-3700.37 h60
  text "Constant" at 6458.85,-3700.37 h60
  text "Board Layer Stack" at 7028.71,-3700.37 h60
  text "1" at 3609.59,-3820.37 h60
  text "Top Overlay" at 4019.5,-3820.37 h60
  text "2" at 3609.59,-3940.37 h60
  text "Top Solder" at 4019.5,-3940.37 h60
  text "Solder Resist" at 4949.24,-3940.37 h60
  text "0.40mil" at 5809.01,-3940.37 h60
  text "3.5" at 6458.85,-3940.37 h60
  text "3" at 3609.59,-4060.37 h60
  text "L1-TOP" at 4019.5,-4060.37 h60
  text "Copper" at 4949.24,-4060.37 h60
  text "1.40mil" at 5809.01,-4060.37 h60
  text "4" at 3609.59,-4180.37 h60
  text "Dielectric1" at 4019.5,-4180.37 h60
  text "IT180A" at 4949.24,-4180.37 h60
  text "5.08mil" at 5809.01,-4180.37 h60
  text "4.2" at 6458.85,-4180.37 h60
  text "5" at 3609.59,-4300.37 h60
  text "L2-GND" at 4019.5,-4300.37 h60
  text "Copper" at 4949.24,-4300.37 h60
  text "1.40mil" at 5809.01,-4300.37 h60
  text "6" at 3609.59,-4420.37 h60
  text "Dielectric 2" at 4019.5,-4420.37 h60
  text "IT180A" at 4949.24,-4420.37 h60
  text "44.49mil" at 5809.01,-4420.37 h60
  text "4.2" at 6458.85,-4420.37 h60
  text "7" at 3609.59,-4540.37 h60
  text "L3-PWR" at 4019.5,-4540.37 h60
  text "Copper" at 4949.24,-4540.37 h60
  text "1.42mil" at 5809.01,-4540.37 h60
  text "8" at 3609.59,-4660.37 h60
  text "Dielectric 3" at 4019.5,-4660.37 h60
  text "IT180A" at 4949.24,-4660.37 h60
  text "5.08mil" at 5809.01,-4660.37 h60
  text "4.2" at 6458.85,-4660.37 h60
  text "9" at 3609.59,-4780.37 h60
  text "L4-BOT" at 4019.5,-4780.37 h60
  text "Copper" at 4949.24,-4780.37 h60
  text "1.40mil" at 5809.01,-4780.37 h60
  text "10" at 3609.59,-4900.37 h60
  text "Bottom Solder" at 4019.5,-4900.37 h60
  text "Solder Resist" at 4949.24,-4900.37 h60
  text "0.40mil" at 5809.01,-4900.37 h60
  text "3.5" at 6458.85,-4900.37 h60
  text "11" at 3609.59,-5020.37 h60
  text "Bottom Overlay" at 4019.5,-5020.37 h60
Doc-Assy-Top:
  lines w2.54: -324.79,359.76 -223.08,359.76 ; -324.79,1440.4 -223.08,1440.4 ; -324.79,2521.03 -223.08,2521.03 ; 971.97,-619.17 971.97,-517.46 ; 971.97,3398.26 971.97,3499.96 ; 2370.44,-619.17 2370.44,-517.46 ; 2370.44,3398.26 2370.44,3499.96 ; 2777.27,-619.17 5065.68,-619.17 ; 3440.23,-517.32 3440.23,-154.86 4963.55,-154.86 ; 3440.23,-395 4963.55,-395 ; 3670.11,-517.32 3670.11,-395 ; 3768.91,-619.17 3768.91,-517.46 ; 3768.91,3398.26 3768.91,3499.96 ; 4026.77,-517.32 4026.77,-395 ; 4098.08,-394.85 4098.08,-154.86 ; 4554,-517.32 4554,-395 ; 4963.97,359.76 5065.68,359.76 ; 4963.97,1440.4 5065.68,1440.4 ; 4963.97,2521.03 5065.68,2521.03 ; 5065.68,-619.17 5065.68,3499.96 -324.79,3499.96 -324.79,-619.17 5065.68,-619.17 ; -223.08,-517.46 -223.08,3398.26 4963.97,3398.26 4963.97,-517.46 -223.08,-517.46
  text "1" at 260.71,3432.91 h35.6
  text "2" at 1659.51,3432.91 h35.6
  text "3" at 3055.44,3432.91 h35.6
  text "4" at 4454.42,3432.91 h35.6
  text "A" at -288.25,3015.33 h35.6
  text "A" at 5003.71,3015.33 h35.6
  text "B" at -288.25,1934.69 h35.6
  text "B" at 5003.71,1934.69 h35.6
  text "C" at -288.25,854.06 h35.6
  text "C" at 5003.71,854.06 h35.6
  text "TITLE:" at 3479.71,-194.88 h22.87
  text "Opal Kelly" at 4138.1,-210.89 h35.58
  text "D" at -288.25,-224.03 h35.6
  text "D" at 5003.71,-224.03 h35.6
  text "13500 SW 72nd Ave Suite 100" at 4138.1,-270.93 h35.58
  text "Portland, OR 97223" at 4138.1,-320.96 h35.58
  text "'.Assembly_Part_Num' / Assembly Drawing" at 3496.16,-321.81 h35.58
  text "www.opalkelly.com" at 4138.1,-370.99 h35.58
  text "(Top)" at 3496.16,-379.76 h35.58
  text "REV:" at 3468.53,-428.89 h22.87
  text "SIZE:" at 3701.13,-428.89 h22.87
  text "ENGINEER:" at 4057.78,-428.89 h22.87
  text "DATE:" at 4585.01,-428.89 h22.87
  text "'.Assembly_Revision_Major'" at 3499.54,-490.92 h35.58
  text "ANSI A" at 3732.14,-490.92 h35.58
  text "NDK" at 4088.8,-490.92 h35.58
  text ".PRINT_DATE" at 4616.03,-490.92 h35.58
  text "1" at 260.71,-587.71 h35.6
  text "2" at 1659.51,-587.71 h35.6
  text "3" at 3055.44,-587.71 h35.6
  text "4" at 4454.42,-587.71 h35.6
Doc-Assy-Bot:
  lines w2.54: -324.57,360.19 -222.86,360.19 ; -324.57,1440.87 -222.86,1440.87 ; -324.57,2521.55 -222.86,2521.55 ; -222.43,-394.61 1300.95,-394.61 ; -222.43,-154.45 1300.95,-154.45 1300.95,-516.93 ; 187.13,-516.93 187.13,-394.61 ; 643.07,-394.45 643.07,-154.45 ; 714.38,-516.93 714.38,-394.61 ; 972.25,-618.78 972.25,-517.07 ; 972.25,3398.81 972.25,3500.52 ; 1071.05,-516.93 1071.05,-394.61 ; 1963.93,-618.78 -324.57,-618.78 ; 2370.78,-618.78 2370.78,-517.07 ; 2370.78,3398.81 2370.78,3500.52 ; 3769.31,-618.78 3769.31,-517.07 ; 3769.31,3398.81 3769.31,3500.52 ; 4964.41,360.19 5066.12,360.19 ; 4964.41,1440.87 5066.12,1440.87 ; 4964.41,2521.55 5066.12,2521.55 ; -324.57,-618.78 5066.12,-618.78 5066.12,3500.52 -324.57,3500.52 -324.57,-618.78 ; -222.86,-517.07 4964.41,-517.07 4964.41,3398.81 -222.86,3398.81 -222.86,-517.07
  text "4" at 286.71,3433.47 h35.6
  text "3" at 1685.75,3433.47 h35.6
  text "2" at 3081.74,3433.47 h35.6
  text "1" at 4480.6,3433.47 h35.6
  text "A" at -262.6,3015.87 h35.6
  text "A" at 5029.58,3015.87 h35.6
  text "B" at -262.6,1935.19 h35.6
  text "B" at 5029.58,1935.19 h35.6
  text "C" at -262.6,854.51 h35.6
  text "C" at 5029.58,854.51 h35.6
  text "TITLE:" at 1261.47,-194.48 h22.87
  text "Opal Kelly" at 603.04,-210.49 h35.58
  text "D" at -262.6,-223.63 h35.6
  text "D" at 5029.58,-223.63 h35.6
  text "13500 SW 72nd Ave Suite 100" at 603.04,-270.53 h35.58
  text "Portland, OR 97223" at 603.04,-320.56 h35.58
  text "'.Assembly_Part_Num' / Assembly Drawing" at 1245.01,-321.41 h35.58
  text "www.opalkelly.com" at 603.04,-370.59 h35.58
  text "(Bottom)" at 1245.01,-379.36 h35.58
  text "DATE:" at 156.12,-428.5 h22.87
  text "ENGINEER:" at 683.37,-428.5 h22.87
  text "SIZE:" at 1040.04,-428.5 h22.87
  text "REV:" at 1272.65,-428.5 h22.87
  text ".PRINT_DATE" at 125.1,-490.53 h35.58
  text "NDK" at 652.35,-490.53 h35.58
  text "ANSI A" at 1009.02,-490.53 h35.58
  text "'.Assembly_Revision_Major'" at 1241.64,-490.53 h35.58
  text "4" at 286.71,-587.33 h35.6
  text "3" at 1685.75,-587.33 h35.6
  text "2" at 3081.74,-587.33 h35.6
  text "1" at 4480.6,-587.33 h35.6
Doc-Fab:
  lines w5: -1048.9,89.94 -848.9,89.94 ; -1048.9,2214.94 -848.9,2214.94 ; -1048.9,4339.94 -848.9,4339.94 ; 1501.1,-1835.06 1501.1,-1635.06 ; 1501.1,6064.94 1501.1,6264.94 ; 4251.1,-1835.06 4251.1,-1635.06 ; 4251.1,6064.94 4251.1,6264.94 ; 4812.81,-1634.55 4812.81,-578.41 9352,-578.41 ; 4812.81,-971 6572.81,-971 ; 4812.81,-658.41 6572.81,-658.41 ; 4813,-768.41 6573,-768.41 ; 5051.1,-1835.06 9551.1,-1835.06 ; 5232.81,-1634.55 5232.81,-578.41 ; 6572.81,-1634.55 6572.81,-578.41 ; 6572.81,-1438.41 9352.81,-1438.41 ; 6572.81,-998.41 9352,-998.41 ; 7001.1,-1835.06 7001.1,-1635.06 ; 7001.1,6064.94 7001.1,6264.94 ; 7132.81,-1634.55 7132.81,-1438.41 ; 7812.81,-1438.41 7812.81,-998.41 ; 8462.81,-1634.55 8462.81,-1438.41 ; 9351.1,89.94 9551.1,89.94 ; 9351.1,2214.94 9551.1,2214.94 ; 9351.1,4339.94 9551.1,4339.94 ; 9551.1,-1835.06 -1048.9,-1835.06 -1048.9,6264.94 9551.1,6264.94 9551.1,-1835.06 ; -848.9,-1635.06 9351.1,-1635.06 9351.1,6064.94 -848.9,6064.94 -848.9,-1635.06
  text "1" at 102.44,6133.09 h70
  text "2" at 2853.1,6133.09 h70
  text "3" at 5598.1,6133.09 h70
  text "4" at 8349.11,6133.09 h70
  text "A" at -977.05,5311.94 h70
  text "A" at 9429.25,5311.94 h70
  text "B" at -977.05,3186.94 h70
  text "B" at 9429.25,3186.94 h70
  text "C" at -977.05,1061.94 h70
  text "C" at 9429.25,1061.94 h70
  text "REVISION:" at 4841.81,-638.41 h40
  text "DESCRIPTION:" at 5271.81,-638.41 h40
  text "PART NUMBER:" at 6652.81,-718.41 h75
  text "20171215" at 4842.81,-738.41 h50
  text "Initial release" at 5272.81,-738.41 h50
  text "'.PCB_Part_Num'-'.PCB_Revision'" at 6672.81,-998.41 h130
  text "D" at -977.05,-1058.06 h70
  text "D" at 9429.25,-1058.06 h70
  text "TITLE:" at 6632.81,-1078.41 h40
  text "Opal Kelly" at 7872.81,-1098.41 h60
  text "13500 SW 72nd Ave Suite 100" at 7872.81,-1198.41 h60
  text "Portland, OR 97223" at 7872.81,-1298.41 h60
  text "'.Assembly_Part_Num' / Fabrication Drawing" at 6672.81,-1378.41 h60
  text "www.opalkelly.com" at 7872.81,-1398.41 h60
  text "SIZE:" at 6632.81,-1498.41 h40
  text "ENGINEER:" at 7192.81,-1498.41 h40
  text "DATE:" at 8512.81,-1498.41 h40
  text "ANSI A" at 6672.81,-1598.41 h60
  text "NDK" at 7232.81,-1598.41 h60
  text ".PRINT_DATE" at 8552.81,-1598.41 h60
  text "1" at 102.44,-1773.21 h70
  text "2" at 2853.1,-1773.21 h70
  text "3" at 5598.1,-1773.21 h70
  text "4" at 8349.11,-1773.21 h70

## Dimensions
0,0 to 118.11,3031.5 on MTG Locations
0,0 to 118.11,118.11 on MTG Locations
0,0 to 4606.3,118.11 on MTG Locations
0,0 to 118.11,118.11 on MTG Locations
0,0 to 4724.41,0 on Dimensions
0,0 to 0,3149.61 on Dimensions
